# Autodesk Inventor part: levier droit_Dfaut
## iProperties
Created: 2006-03
Part Number: levier droit_Dfaut
Document SubType Name: Modeling
Designer: Flavien MARTY
Author: Flavien MARTY
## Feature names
1. Base1
